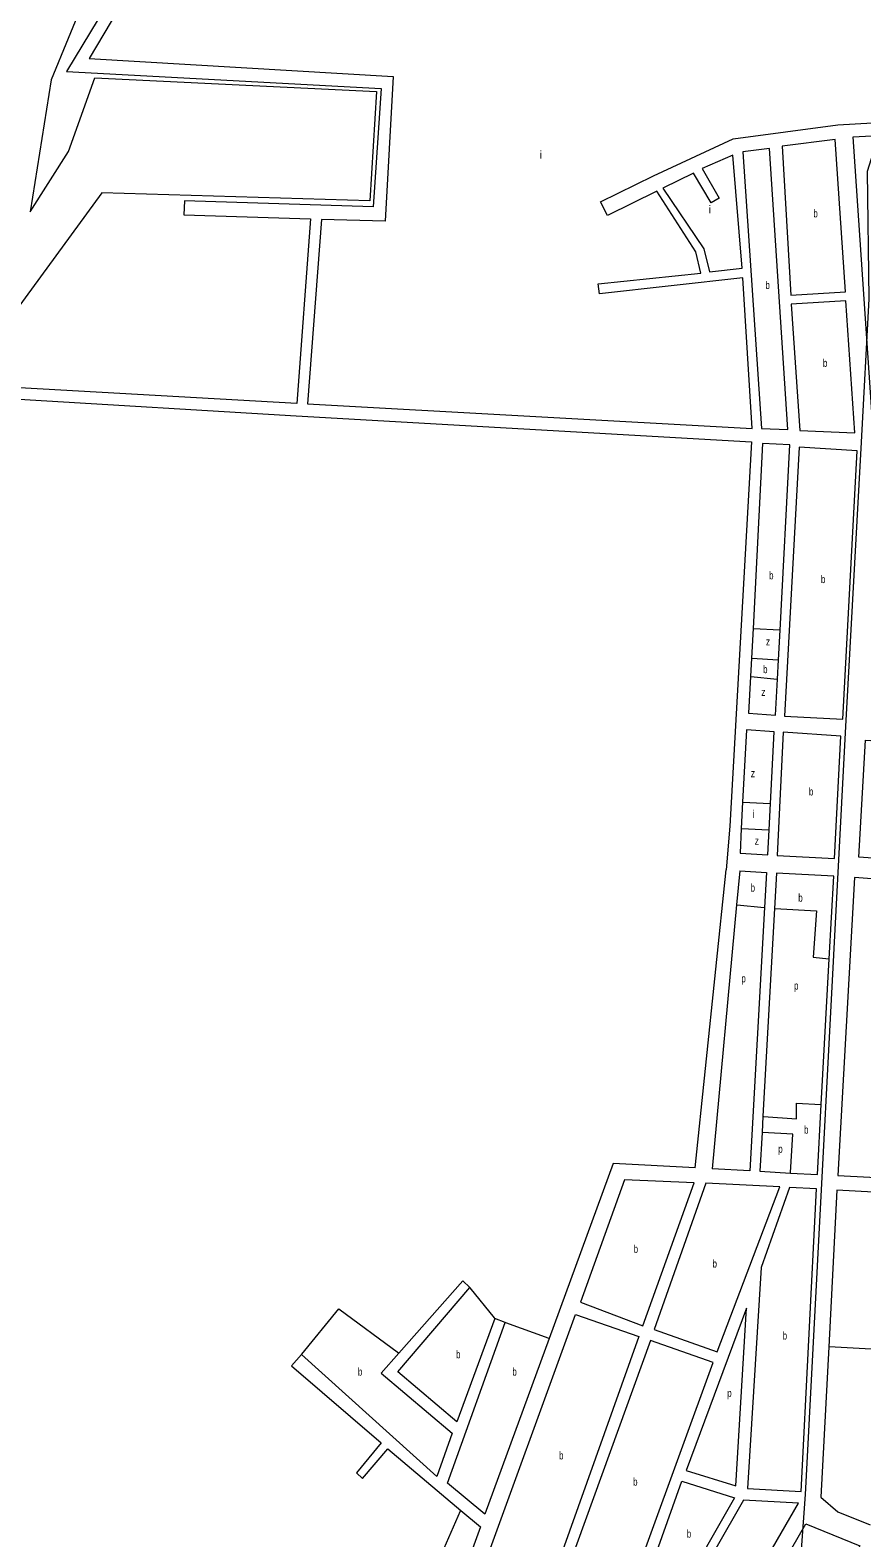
# Model space of a CAD drawing. Extents: x 639657 to 671642, y 222838 to 252123.
# Drawn here: x 650477 to 651541, y 230977 to 232905 of the extents above; entities that cross this region are included whole.
import ezdxf

# ---------------------------------------------------------------- set-up
doc = ezdxf.new("R2010")
doc.units = 0
doc.header["$LTSCALE"] = 4
for name, color, linetype, lineweight in [('1', 7, 'Continuous', 13), ('21', 7, 'Continuous', 13), ('5', 7, 'Continuous', 13), ('57', 7, 'Continuous', 35)]:
    doc.layers.add(name, color=color, linetype=linetype, lineweight=lineweight)
doc.layers.add('7', color=7, linetype='Continuous')

msp = doc.modelspace()

# ---------------------------------------------------------------- linework, layer by layer
at = {"layer": '1'}
for p, q in [((651327.652, 231450.233), (651367.54, 231831.35)), ((651410.51, 231445.88), (651449.66, 231443.686)), ((650997.511, 231055.743), (650824.24, 231211.81))]:
    msp.add_line(p, q, dxfattribs=at)
for points in [[(651605.149, 233596.585), (651606.61, 233541.11), (651784.96, 233458.23), (651833.35, 233458.23), (651854.29, 232792.55), (651598.23, 233016.07), (651494.34, 233052.42), (650673.45, 233099.62), (650523.71, 232852.01), (650926.07, 232829.98), (650916.16, 232678.74), (650674.55, 232686.58), (650674.11, 232668.8), (650835.84, 232663.38), (650818.41, 232427.49), (650463.92, 232447.36), (650463.56, 232432.85), (650817.36, 232411.52), (651399.82, 232378.53), (651371.87, 231887.13), (651367.54, 231831.35)], [(651436.275, 232137.873), (651448.79, 232374.61), (651413.89, 232376.51), (651401.668, 232139.971), (651399.71, 232102.088), (651398.499, 232078.647), (651396.07, 232031.64)], [(651396.07, 232031.64), (651430.52, 232029.02), (651432.952, 232075.018), (651434.269, 232099.927), (651436.275, 232137.873)], [(651393.25, 232010.44), (651388.422, 231917.827), (651386.666, 231884.144)], [(651423.863, 231915.96), (651428.53, 232007.74), (651393.25, 232010.44)], [(651386.666, 231884.144), (651385.03, 231852.76), (651420.53, 231850.43), (651422.149, 231882.275), (651423.863, 231915.96)], [(651384.807, 231830.203), (651380.731, 231786.382), (651349.359, 231449.075)], [(651384.807, 231830.203), (651419.04, 231827.93), (651416.534, 231783.221)], [(651499.043, 231717.31), (651504.81, 231823.24), (651431.56, 231827.14), (651429.056, 231781.791), (651414.391, 231516.169), (651413.253, 231495.554), (651410.51, 231445.88)], [(651416.534, 231783.221), (651397.66, 231446.5), (651349.359, 231449.075)], [(651449.66, 231443.686), (651484.04, 231441.76), (651488.907, 231531.146), (651499.043, 231717.31)], [(651327.652, 231450.233), (651223.06, 231455.81), (651141.237, 231232.337)], [(651618.44, 231415.89), (651508.88, 231421.76), (651498.494, 231221.42)], [(651071.54, 231257.89), (651022.76, 231125.75), (650947.7, 231189.71), (651039.79, 231297.33)], [(651039.79, 231297.33), (651030.66, 231305.74), (650948.847, 231213.33)], [(651141.237, 231232.337), (651058.87, 231007.38), (651011.23, 231047.09), (651084.59, 231252.72), (651071.54, 231257.89)], [(651498.494, 231221.42), (651488.54, 231029.41), (651509.99, 231010.67), (651551.311, 230993.942)], [(650824.24, 231211.81), (650811.54, 231197.09), (650926.25, 231098.95)], [(650948.847, 231213.33), (650926.175, 231187.721), (651016.894, 231111.153), (650997.511, 231055.743)], [(650926.25, 231098.95), (650894.65, 231060.39), (650902.55, 231053.08), (650934.72, 231091.25), (651028.077, 231012.432)], [(651028.077, 231012.432), (651053.19, 230991.23), (651023.64, 230910.24)]]:
    msp.add_lwpolyline(points, dxfattribs=at)
for points in [[(650831.88, 232426.88), (651400.42, 232395.71), (651388.71, 232587.99), (651205.24, 232567.65), (651203.82, 232580.37), (651334.97, 232594.21), (651328.44, 232621.41), (651278.51, 232698.89), (651215.82, 232667.93), (651206.8, 232685.18), (651274.22, 232718.49), (651376.17, 232765.73), (651509.91, 232783.92), (651606.22, 232789.3), (651830.66, 232784.59), (651599.65, 233000.8), (651494.24, 233038.76), (650681.37, 233085.46), (650552.86, 232868.54), (650941.47, 232845.35), (650931.35, 232660.37), (650849.93, 232662.48)], [(651438.94, 232756.58), (651449.96, 232565.8), (651520.02, 232570.09), (651506.7, 232765.12)], [(651607.64, 232772.45), (651631.84, 232435.61), (651613.21, 232435.86), (651598.01, 232434.58), (651575.23, 232422.95), (651563.86, 232415.94), (651554.39, 232404.22), (651529.89, 232768.3)], [(651286.46, 232702.86), (651338.96, 232625.03), (651346.22, 232595.9), (651387.71, 232600.33), (651375.8, 232745.1), (651336.57, 232728.01), (651358.3, 232690.08), (651348.3, 232683.87), (651325.69, 232721.91)], [(651388.82, 232749.25), (651412.72, 232395.52), (651446.33, 232394.09), (651422.71, 232753.4)], [(651450.47, 232554.42), (651461.42, 232393.1), (651531.82, 232389.99), (651520.53, 232558.61)], [(651442.1, 232027.82), (651516.66, 232023.92), (651534.66, 232367.07), (651460.56, 232371.84)], [(651440.35, 232007.1), (651432.72, 231849.8), (651505.71, 231845.63), (651513.88, 232002.08)], [(651545.48, 231997), (651721.02, 231985.99), (651713.36, 231834.9), (651536.78, 231847.28)], [(651510.14, 231440.39), (651591.98, 231436.05), (651614.71, 231814.89), (651531.35, 231821.67)], [(651237.39, 231434.92), (651180.97, 231278.65), (651260.97, 231248.52), (651326.49, 231431.06)], [(651341.52, 231430.58), (651275.07, 231243.74), (651355.76, 231215.17), (651435.78, 231425.84)], [(651448.4, 231425.02), (651411.94, 231322.91), (651394.61, 231040.48), (651463.1, 231036.58), (651482.78, 231423.39)], [(651133.8, 230892.43), (651050.8, 230921.74), (651174.91, 231262.71), (651255.86, 231234.79)], [(651316.01, 231063.32), (651379.72, 231043.7), (651393.26, 231271.12)], [(651146.32, 230886.17), (651225.79, 230858.49), (651350.65, 231201.34), (651270.77, 231229.53)], [(651307.706, 230905.464), (651267.39, 230927.51), (651310.79, 231049.59), (651378, 231028.6)], [(651316.97, 230898.8), (651371.39, 230868.27), (651459.93, 231021.58), (651389.36, 231025.36)], [(651182.62, 230497.65), (651469.14, 230995.07), (651538.28, 230967.06), (651341.8, 230621.31), (651368.86, 230595.04), (651244.95, 230450.53)]]:
    msp.add_lwpolyline(points, close=True, dxfattribs=at)
at = {"layer": '21'}
for points in [[(651401.668, 232139.971), (651402.168, 232139.941), (651435.775, 232137.903), (651436.275, 232137.873)], [(651399.71, 232102.088), (651400.21, 232102.057), (651433.769, 232099.958), (651434.269, 232099.927)], [(651398.499, 232078.647), (651398.999, 232078.594), (651432.452, 232075.071), (651432.952, 232075.018)], [(651388.422, 231917.827), (651388.922, 231917.801), (651423.363, 231915.986), (651423.863, 231915.96)], [(651386.666, 231884.144), (651387.166, 231884.118), (651421.649, 231882.301), (651422.149, 231882.275)], [(651380.731, 231786.382), (651381.231, 231786.338), (651416.034, 231783.265), (651416.534, 231783.221)], [(651429.056, 231781.791), (651429.556, 231781.764), (651482.989, 231778.848), (651478.374, 231719.743), (651498.543, 231717.369), (651499.043, 231717.31)], [(651414.391, 231516.169), (651414.891, 231516.131), (651457.146, 231512.879), (651457.146, 231533.196), (651488.407, 231531.178), (651488.907, 231531.146)], [(651449.66, 231443.686), (651449.689, 231444.186), (651452.531, 231493.485), (651413.753, 231495.528), (651413.253, 231495.554)], [(651071.54, 231257.89), (651071.137, 231258.39), (651040.193, 231296.83), (651039.79, 231297.33)], [(650824.24, 231211.81), (650824.65, 231212.31), (650871.989, 231269.995), (650948.347, 231213.699), (650948.847, 231213.33)], [(651084.59, 231252.72), (651085.09, 231252.54), (651140.737, 231232.517), (651141.237, 231232.337)], [(651607.444, 231215.364), (651606.944, 231215.392), (651498.994, 231221.392), (651498.494, 231221.42)], [(651023.64, 230910.24), (651023.14, 230910.554), (650991.973, 230930.146), (651027.858, 231011.932), (651028.077, 231012.432)]]:
    msp.add_lwpolyline(points, dxfattribs=at)
at = {"layer": '5'}
for points in [[(650547.91, 232947.52), (650504.41, 232841.23), (650477.58, 232672.4)], [(650560.04, 232843.68), (650920.46, 232826.13), (650911.69, 232686.59), (650568.99, 232696.99), (650431.47, 232508.71)], [(650477.58, 232672.4), (650526.39, 232749.48), (650560.04, 232843.68)]]:
    msp.add_lwpolyline(points, dxfattribs=at)
at = {"layer": '57', "lineweight": 13}
msp.add_lwpolyline([(651773.011, 234750.407), (651803.088, 233802.52), (651824.392, 233344.878), (651834.418, 233046.469), (651800.582, 232947.418), (651773.012, 232904.788), (651712.859, 232864.666), (651627.642, 232834.575), (651569.995, 232794.452), (651547.438, 232724.239), (651549.945, 232561.242), (651539.919, 232378.185), (651519.868, 232014.578), (651468.488, 231032.839), (651460.969, 230932.533), (651410.841, 230809.659)], dxfattribs=at)

# ---------------------------------------------------------------- texts
at = {"layer": '7'}
for p in [(651128.821, 232740.585), (651345.113, 232670.5), (651400.978, 231897.761)]:
    msp.add_text('i', height=10, dxfattribs=at).set_placement(p)
for s, width, p in [('b', 0.75, (651478.855, 232665.46)), ('b', 0.75, (651417.599, 232573.745)), ('b', 0.75, (651491.042, 232474.3)), ('b', 0.75, (651422.309, 232202.765)), ('b', 0.75, (651488.505, 232197.88)), ('z', 0.8, (651418.123, 232118.15)), ('b', 0.75, (651414.64, 232082.723)), ('z', 0.8, (651412.262, 232053.641)), ('z', 0.8, (651398.865, 231949.756)), ('b', 0.75, (651473.18, 231926.365)), ('z', 0.8, (651403.889, 231863.465)), ('b', 0.75, (651398.656, 231803.451)), ('b', 0.75, (651459.572, 231790.522)), ('p', 0.75, (651386.867, 231687.481)), ('p', 0.75, (651454.243, 231678.246)), ('b', 0.75, (651466.955, 231494.077)), ('p', 0.75, (651433.938, 231469.534)), ('b', 0.75, (651249.082, 231341.72)), ('b', 0.75, (651349.942, 231322.875)), ('b', 0.75, (651439.635, 231230.8)), ('b', 0.75, (651022.034, 231206.888)), ('b', 0.75, (650896.511, 231184.724)), ('b', 0.75, (651094.025, 231184.724)), ('p', 0.75, (651368.739, 231157.41)), ('b', 0.75, (651153.664, 231077.57)), ('b', 0.75, (651248.441, 231044.01)), ('b', 0.75, (651317.008, 230977.527))]:
    msp.add_text(s, height=10, dxfattribs=dict(at, width=width)).set_placement(p)

doc.saveas('drawing.dxf')
